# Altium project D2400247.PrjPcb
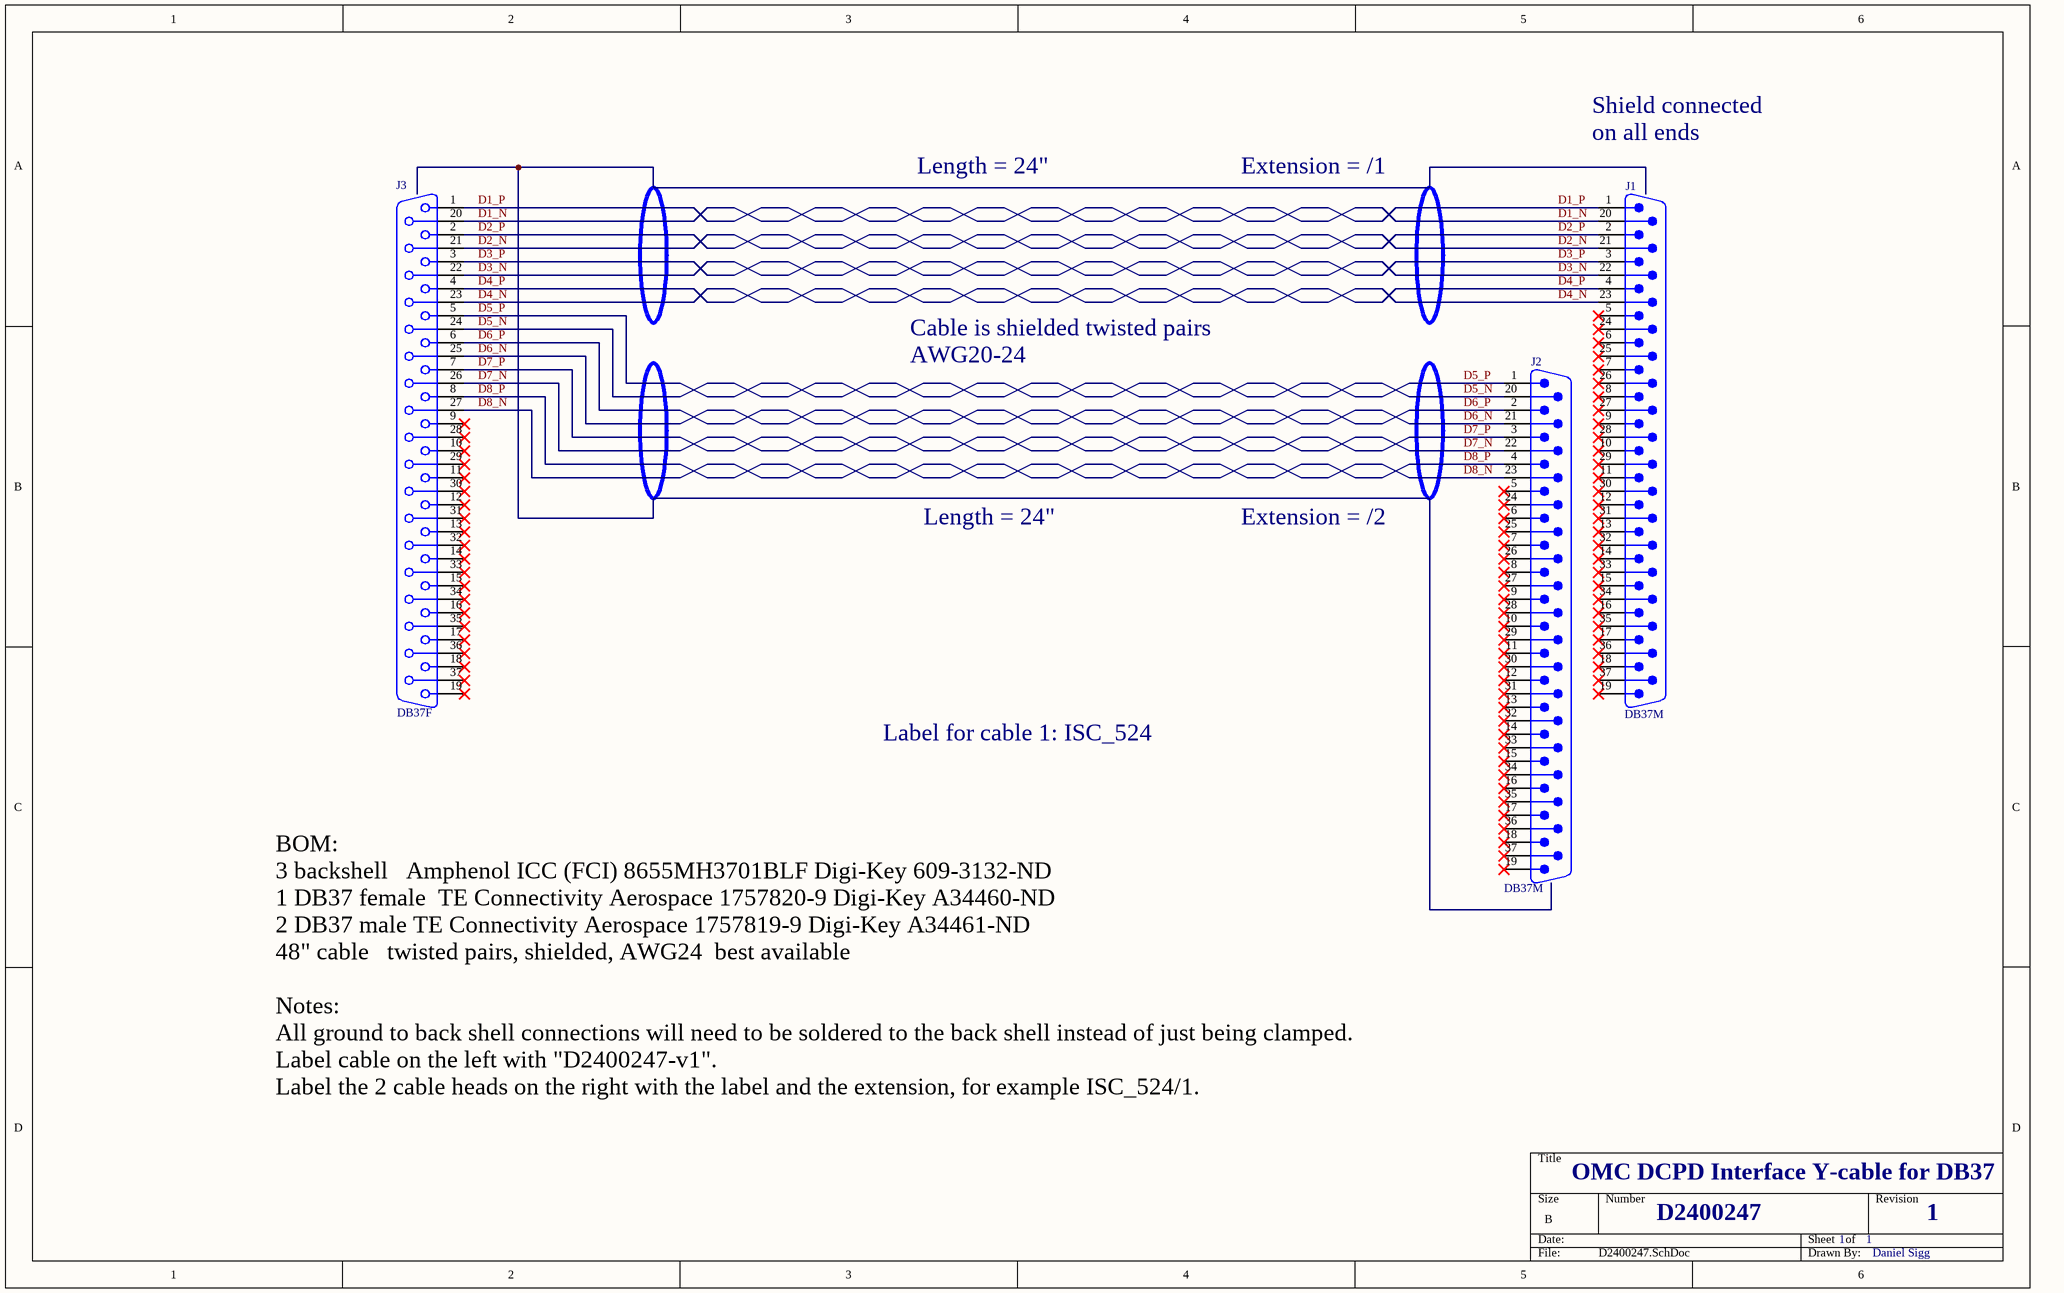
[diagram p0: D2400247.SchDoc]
1 sheet, 3 parts. Net scope: global (net labels, ports and power ports of the same name join across sheets).

## Sheet D2400247.SchDoc
size B; SheetNumber: 1; SheetTotal: 1; PageSetup: Record=PageOptions¦CenterHorizontal=True¦CenterVertical=True¦PrintScale=1.12¦XCorrection=1.00¦YCorrection=1.00¦PrintKind=0¦BorderSize=5000000¦LeftOffset=0¦BottomOffset=0¦Orientation=2¦PaperLength=1000¦PaperWidth=1000¦Scale=100¦PaperSource=7¦PrintQuality=-4¦MediaType=1¦DitherType=10¦PaperKind=Tabloid¦PrintScaleMode=1

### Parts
J1  DB37M  [DB37M-RA]
J2  DB37M  [DB37M-RA]
J3  DB37F  [DB37F-RA]

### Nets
D1_N: J1.20 J3.20
D1_P: J1.1 J3.1
D2_N: J1.21 J3.21
D2_P: J1.2 J3.2
D3_N: J1.22 J3.22
D3_P: J1.3 J3.3
D4_N: J1.23 J3.23
D4_P: J1.4 J3.4
D5_N: J2.20 J3.24
D5_P: J2.1 J3.5
D6_N: J2.21 J3.25
D6_P: J2.2 J3.6
D7_N: J2.22 J3.26
D7_P: J2.3 J3.7
D8_N: J2.23 J3.27
D8_P: J2.4 J3.8

Not connected (* = marked no-connect by the designer): J1 5* 6* 7* 8* 9* 10* 11* 12* 13* 14* 15* 16* 17* 18* 19* 24* 25* 26* 27* 28* 29* 30* 31* 32* 33* 34* 35* 36* 37* 38 39; J2 5* 6* 7* 8* 9* 10* 11* 12* 13* 14* 15* 16* 17* 18* 19* 24* 25* 26* 27* 28* 29* 30* 31* 32* 33* 34* 35* 36* 37* 38 39; J3 9* 10* 11* 12* 13* 14* 15* 16* 17* 18* 19* 28* 29* 30* 31* 32* 33* 34* 35* 36* 37* 38 39

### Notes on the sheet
- Shield connected
- on all ends
- Length = 24"
- Extension = /1
- Cable is shielded twisted pairs
- AWG20-24
- Extension = /2
- Label for cable 1: ISC_524
- BOM:
  3	backshell 		Amphenol ICC (FCI) 8655MH3701BLF	Digi-Key 609-3132-ND
  1	DB37 female 	TE Connectivity Aerospace 1757820-9	Digi-Key A34460-ND
  2	DB37 male	TE Connectivity Aerospace 1757819-9	Digi-Key A34461-ND
  48"	cable 		twisted pairs, shielded, AWG24		best available
  Notes:
  All ground to back shell connections will need to be soldered to the back shell instead of just being clamped.
  Label cable on the left with "D2400247-v1".
  Label the 2 cable heads on the right with the label and the extension, for example ISC_524/1.
- OMC DCPD Interface Y-cable for DB37
- D2400247
- 1
- Daniel Sigg

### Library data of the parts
J1 J2 = DB37M: Plug Assembly, 37 Position, Right Angle, .318 Series; Part Number: A32104-ND
J3 = DB37F: Receptacle Assembly, 37 Position, Right Angle, .318 Series; Part Number: A32130-ND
